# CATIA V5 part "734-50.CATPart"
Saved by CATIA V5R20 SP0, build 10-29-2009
Part number: 734-50
Bounding box of the stored display mesh (mm): x -40 to 40, y -40 to 40, z -60 to 71
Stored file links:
  C:\Users\Utente\Desktop\IO LAVORO\3D X SITO CF\X SITO\734\734-50.CATPart
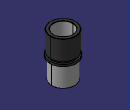
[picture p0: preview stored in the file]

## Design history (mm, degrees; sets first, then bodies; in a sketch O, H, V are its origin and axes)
Set1
  DatumSurface1 to DatumSurface25 "734-50"
Body1 (main body)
